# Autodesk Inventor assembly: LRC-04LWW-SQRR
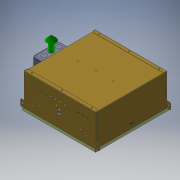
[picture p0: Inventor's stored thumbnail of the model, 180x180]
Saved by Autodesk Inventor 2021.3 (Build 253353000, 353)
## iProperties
load_classification: Lighting
motor: 0 ul
Part Number: LRC-04LWW-SQRR
Document SubType Name: Assembly
Designer: JChurch
description: 0:0:Lensed 4" Wall Wash - COB LED
manufacturer: 0:0:The Kirlin Company
model: 0:0:LRC-04LWW
url: 0:0:
Author: JChurch
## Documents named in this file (6)
- X:\Revit Files\0000-Un-Zipped\COB\LRC-04LWW-SQR\LRC-04LWW-SQRR.iam
- X:\INVENTOR\830\830557-00-00.iam
- X:\INVENTOR\881\881088-00-00.iam
- X:\INVENTOR\750\750477-00-XX.iam
- X:\INVENTOR\725\725278-01-00.ipt
- X:\Revit Files\0000-Un-Zipped\COB\LRC-04LWW-SQR\LRC-04LWW-SQRR_Substitute_1.ipt
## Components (5 placed, 5 different names)
1. 830557-00-00:1 [sub-assembly] — Mate:1, Mate:2, Mate:3, Tangent:1, Mate:4, Angle:1, Mate:5
2. 881088-00-00:1 [sub-assembly] — Tangent:1, Mate:4, Angle:1
3. 750477-00-XX:1 [sub-assembly] — Mate:5, Mate:6, Flush:1, Flush:8, Mate:7, Mate:8
4. 725278-01-00:1 — Flush:8, Mate:7, Mate:8
5. LRC-04LWW-SQRR_Substitute_1:1
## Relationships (12: Mate 8, Flush 2, Tangent 1, Angle 1)
- Mate:1: 830557-00-00:1
- Mate:2: 830557-00-00:1
- Mate:3: 830557-00-00:1
- Tangent:1: 830557-00-00:1 ↔ 881088-00-00:1
- Mate:4: 830557-00-00:1 ↔ 881088-00-00:1
- Angle:1: 830557-00-00:1 ↔ 881088-00-00:1
- Mate:5: 830557-00-00:1 ↔ 750477-00-XX:1
- Mate:6: 750477-00-XX:1
- Flush:1: 750477-00-XX:1
- Flush:8: 750477-00-XX:1 ↔ 725278-01-00:1
- Mate:7: 750477-00-XX:1 ↔ 725278-01-00:1
- Mate:8: 750477-00-XX:1 ↔ 725278-01-00:1
